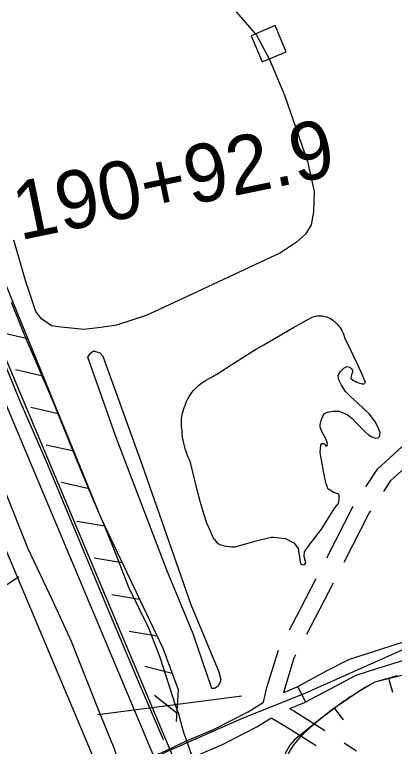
# Model space of a CAD drawing. Extents: x 3598634 to 3636690, y 517270 to 542944.
# Drawn here: x 3630353 to 3631009, y 526474 to 527737 of the extents above; entities that cross this region are included whole.
import ezdxf

# ---------------------------------------------------------------- set-up
doc = ezdxf.new("R2010")
doc.units = 0
for name, color, linetype in [('V-BLDG-OTLN', 7, 'Continuous'), ('V-BORW-LINE', 7, 'Continuous'), ('V-FLOD-BASE', 7, 'Continuous'), ('V-LEVE-TOET', 7, 'Continuous'), ('V-ROAD-CNTR', 7, 'Continuous'), ('V-RRAP-FSHR', 7, 'Continuous'), ('V-SITE-VEGE', 7, 'Continuous'), ('V-SURV-IDEN', 7, 'Continuous'), ('V-SURV-LINE', 7, 'Continuous'), ('V-TOPO-SHOR', 7, 'Continuous'), ('V-UTIL-LINE', 7, 'Continuous')]:
    doc.layers.add(name, color=color, linetype=linetype)

msp = doc.modelspace()

# ---------------------------------------------------------------- linework, layer by layer
at = {"layer": 'V-BLDG-OTLN'}
msp.add_lwpolyline([(3630802.8, 527718.4), (3630761.5, 527700.9), (3630780.7, 527655.9), (3630822, 527673.4)], close=True, dxfattribs=at)
at = {"layer": 'V-BORW-LINE'}
for p, q in [((3630998.6, 526592), (3631005.6, 526568.1)), ((3630905.2, 526539.8), (3630920.4, 526520))]:
    msp.add_line(p, q, dxfattribs=at)
for points in [[(3630975, 526585.1), (3630958, 526575.8), (3630942, 526565.5), (3630909.5, 526543.1), (3630877.9, 526518.8), (3630836.4, 526485.6), (3630828, 526476.4), (3630820.2, 526461.7), (3630819.3, 526454.1), (3630820.7, 526446.1), (3630839.1, 526398.4), (3630858.5, 526350.5), (3630899.2, 526244.1), (3630940.1, 526137.7), (3630975.5, 526048.3), (3631011.3, 525959)], [(3631013.3, 526596.3), (3630975, 526585.1)]]:
    msp.add_lwpolyline(points, dxfattribs=at)
msp.add_spline([(3630975, 526585.1), (3631052, 526605.2), (3631102.9, 526609.5), (3631126.7, 526580.9), (3631214.4, 526427.2), (3631278, 526221.5), (3631364.1, 526008.1), (3631414.5, 525862.8), (3631469.9, 525728.9), (3631500, 525646), (3631501, 525593.6), (3631358.1, 525555.8), (3631253.3, 525516), (3631197.2, 525519.2), (3631149.8, 525621.4), (3631070.3, 525800.1), (3631011.3, 525959), (3630940.1, 526137.7), (3630858.5, 526350.5), (3630820.7, 526446.1), (3630877.9, 526518.8), (3630942, 526565.5), (3630975, 526585.1)], degree=3, dxfattribs=at)
at = {"layer": 'V-FLOD-BASE'}
msp.add_lwpolyline([(3630610.3, 526485.5), (3630563.4, 526594.3), (3630517.7, 526703.7), (3630465.7, 526828.1), (3630408.7, 526964.2), (3630362.4, 527071.1), (3630323.1, 527165.5), (3630267.9, 527299.7)], dxfattribs=at)
at = {"layer": 'V-LEVE-TOET'}
for points in [[(3630347.1, 527241), (3630360.4, 527208.1), (3630373.9, 527175.3), (3630387.8, 527142.6), (3630401.9, 527110), (3630413.3, 527083.1), (3630424.6, 527056), (3630435.7, 527028.9), (3630446.7, 527001.7), (3630457.5, 526974.5)], [(3630457.5, 526974.5), (3630487.2, 526903.8), (3630508.2, 526854.3), (3630528.4, 526804.1), (3630550, 526748.8), (3630584.3, 526679), (3630603.9, 526628.3), (3630631, 526544.3), (3630636.1, 526530.6), (3630640.4, 526513.1), (3630644.8, 526498.1), (3630648, 526489), (3630654.8, 526469.5), (3630656.8, 526463.6), (3630668.3, 526444), (3630683, 526424.4), (3630709.9, 526379.4), (3630750.5, 526292.7), (3630803.2, 526169.6), (3630835.5, 526091.5), (3630882.4, 525978.8), (3630932, 525870), (3630975.1, 525771), (3631010.7, 525691.5)], [(3631057, 525246.7), (3631002.3, 525362.7), (3630957.8, 525458.5), (3630917.8, 525545.1), (3630874, 525642.2), (3630830.3, 525754.2), (3630789.7, 525844.8), (3630752.9, 525934.6), (3630722.4, 526002.4), (3630678, 526107.9), (3630642.6, 526198.4), (3630593.3, 526333.2), (3630563.5, 526402.2), (3630552.5, 526411.4), (3630546.7, 526421), (3630535.9, 526438.8), (3630525.2, 526471.4), (3630498, 526537.2), (3630451.1, 526655), (3630418.7, 526726.7), (3630376.7, 526815.3), (3630336.8, 526915)]]:
    msp.add_lwpolyline(points, dxfattribs=at)
at = {"layer": 'V-ROAD-CNTR'}
for p, q in [((3630892.1, 526799.8), (3630937.7, 526888.8)), ((3630841.3, 526577.6), (3630855.4, 526551.1)), ((3630922.1, 526480.2), (3630943.3, 526466.3))]:
    msp.add_line(p, q, dxfattribs=at)
for points in [[(3629731.6, 528159), (3630126, 527314.9), (3630608.6, 526171.2)], [(3630959.5, 526922.3), (3630979.8, 526952.7), (3631021.7, 526991.3), (3631027.7, 526993.8)], [(3630990.2, 526914.3), (3631002.7, 526933.1), (3631038.2, 526965.6), (3631065.2, 526977)], [(3630921.9, 526792.3), (3630965.3, 526876.9), (3630968, 526881)], [(3628671, 525631.8), (3630360.2, 526767.2)], [(3630827.5, 526675.6), (3630845.9, 526710.4), (3630873.8, 526764.2)], [(3630857.4, 526668.1), (3630872.5, 526696.5), (3630903.6, 526756.7)], [(3629164.8, 525508.6), (3630029.3, 526089.5), (3630473.4, 526378.3), (3630510.5, 526408.8), (3630615, 526464.9), (3630745.2, 526522.1), (3630855.8, 526566.4), (3631067.5, 526661.3)], [(3630817.8, 526567.4), (3630840.6, 526577.2), (3630892.9, 526605), (3630931.3, 526624.7), (3630967.6, 526636.4), (3631024.7, 526654.6)], [(3630828.5, 526539.4), (3630853.5, 526550.1), (3630906.8, 526578.4), (3630942.8, 526596.9), (3630976.7, 526607.9), (3631034.1, 526626.2), (3631093.1, 526646.5), (3631106, 526651.3)], [(3630782.5, 526550.4), (3630788.8, 526575.7), (3630807.8, 526638.5), (3630808.8, 526640.3)], [(3630817.6, 526567.4), (3630817.7, 526567.8), (3630835.7, 526627), (3630838.7, 526632.8)], [(3630505, 526415.5), (3630539.9, 526434.4), (3630575.1, 526451.2), (3630594.2, 526459.2), (3630606.1, 526463.2), (3630628.1, 526473.6), (3630648.7, 526483.2), (3630697.9, 526504.1), (3630756.2, 526534.1), (3630782.7, 526550.5)], [(3630828.2, 526539.3), (3630835, 526535.4), (3630888.5, 526501.9)], [(3630519.2, 526389.1), (3630553.5, 526407.6), (3630587.4, 526423.8), (3630604.8, 526431.1), (3630617.3, 526435.3), (3630640.9, 526446.5), (3630660.9, 526455.8), (3630710.6, 526476.9), (3630771, 526508), (3630795.2, 526522.9)], [(3630795.8, 526523.3), (3630819.5, 526509.7), (3630873.5, 526475.9)]]:
    msp.add_lwpolyline(points, dxfattribs=at)
at = {"layer": 'V-RRAP-FSHR'}
for p, q in [((3630375.7, 527178), (3630328, 527188.8)), ((3630402.1, 527113.2), (3630354.5, 527124)), ((3630428.6, 527048.4), (3630381, 527059.2)), ((3630455.1, 526983.6), (3630407.5, 526994.4)), ((3630481.6, 526918.8), (3630434, 526929.6)), ((3630508.9, 526854.4), (3630460.7, 526862.5)), ((3630538.9, 526791.1), (3630490.7, 526799.3)), ((3630568.9, 526727.9), (3630520.8, 526736)), ((3630598.9, 526664.6), (3630550.8, 526672.8)), ((3630625.2, 526599.8), (3630577.9, 526612.1)), ((3630633.1, 526531.7), (3630594.7, 526562))]:
    msp.add_line(p, q, dxfattribs=at)
msp.add_lwpolyline([(3630162.5, 527695.8), (3630212.7, 527580.1), (3630326.2, 527299), (3630501.9, 526869), (3630608.9, 526643.7), (3630635.4, 526572.4), (3630632.2, 526517)], dxfattribs=at)
at = {"layer": 'V-SITE-VEGE'}
msp.add_lwpolyline([(3630735.5, 527742.3), (3630770.9, 527702), (3630792.9, 527659.8), (3630818.9, 527598.2), (3630859, 527484), (3630870.4, 527432), (3630868.8, 527397.2), (3630864.9, 527374.5), (3630855.3, 527358.3), (3630839.9, 527344.6), (3630812.3, 527326.1), (3630659.5, 527255.1), (3630580.2, 527217.8), (3630529.3, 527201.5), (3630501.7, 527197.3), (3630472.9, 527194.1), (3630445.2, 527196.6), (3630433.5, 527197.6), (3630416.9, 527200), (3630399.3, 527212.4), (3630389.8, 527224.9), (3630372, 527278.4), (3630351.7, 527347.9)], dxfattribs=at)
msp.add_lwpolyline([(3630479.3, 527145.8), (3630484.3, 527153.2), (3630489.3, 527157.2), (3630500, 527153.8), (3630505.7, 527148), (3630573.2, 526959.4), (3630657.5, 526719.4), (3630705.9, 526602.7), (3630709, 526589.5), (3630708.2, 526585.4), (3630704.8, 526578), (3630698.2, 526573.9), (3630694, 526574), (3630693.2, 526575.6), (3630661.1, 526668.3), (3630616, 526778.4), (3630528.3, 527007.6)], close=True, dxfattribs=at)
at = {"layer": 'V-SURV-LINE'}
for points in [[(3630236.7, 527382.4), (3630828.3, 525975.7)], [(3630800.7, 525964.1), (3630209.1, 527370.8)]]:
    msp.add_lwpolyline(points, dxfattribs=at)
at = {"layer": 'V-TOPO-SHOR'}
for points in [[(3630655.2, 526968.8), (3630653, 526973.5), (3630651, 526978.2), (3630649.2, 526983.1), (3630647.6, 526988), (3630646.2, 526992.9), (3630645, 526997.9), (3630643.9, 527003), (3630643.1, 527008.1), (3630642.5, 527013.2), (3630642.1, 527018.4), (3630641.6, 527022.4), (3630641.2, 527026.6), (3630641.1, 527030.7), (3630641.2, 527034.8), (3630641.4, 527038.9), (3630641.9, 527043), (3630642.6, 527047.1), (3630643.5, 527051.2), (3630644.6, 527055.1), (3630645.9, 527059.1), (3630647.4, 527062.9), (3630648.9, 527066.8), (3630650.5, 527070.7), (3630652.4, 527074.4), (3630654.5, 527078.1), (3630656.7, 527081.6), (3630659.2, 527085), (3630661.8, 527088.3), (3630664.6, 527091.4), (3630667.5, 527094.4), (3630670.6, 527097.2), (3630673.9, 527099.9), (3630677.2, 527102.4), (3630680.8, 527104.7), (3630684.4, 527106.8), (3630694.1, 527112.1), (3630703.7, 527117.7), (3630713.2, 527123.5), (3630727, 527132.7), (3630740.9, 527141.7), (3630754.9, 527150.5), (3630769.1, 527159.1), (3630783.4, 527167.4), (3630799.9, 527177.3), (3630816.5, 527187), (3630833.3, 527196.5), (3630850.1, 527205.9), (3630867, 527215), (3630869.7, 527216), (3630872.4, 527216.7), (3630875.2, 527217.3), (3630878, 527217.6), (3630880.8, 527217.7), (3630883.6, 527217.5), (3630886.4, 527217.1), (3630889.2, 527216.5), (3630891.9, 527215.6), (3630894.5, 527214.6), (3630897, 527213.3), (3630899.9, 527211.6), (3630902.7, 527209.7), (3630905.4, 527207.6), (3630907.9, 527205.3), (3630910.2, 527202.9), (3630912.5, 527200.4), (3630914.5, 527197.7), (3630916.4, 527194.8), (3630918, 527191.9), (3630919.5, 527188.9), (3630920.8, 527185.7), (3630921.9, 527182.5), (3630922.8, 527179.3)], [(3630922.8, 527179.3), (3630930.1, 527164.8), (3630937.2, 527150.3), (3630944.1, 527135.6), (3630950.7, 527120.8), (3630957.1, 527106), (3630957.6, 527105.2), (3630957.9, 527104.3), (3630958.1, 527103.4), (3630958, 527102.5), (3630957.7, 527101.6), (3630957.2, 527100.9), (3630956.5, 527100.2), (3630955.7, 527099.7), (3630954.8, 527099.5), (3630953.9, 527099.4), (3630953, 527099.6), (3630952.2, 527099.9), (3630949.3, 527100.6), (3630946.4, 527101.5), (3630943.7, 527102.6), (3630941, 527103.9), (3630938.4, 527105.4), (3630936, 527107.1), (3630933.7, 527109)], [(3630880.8, 526981.5), (3630882, 526994.4), (3630883.7, 526996.8), (3630887.2, 526997), (3630888.9, 526995.3), (3630891.2, 526992.3), (3630892.7, 526993.2), (3630893.3, 526997), (3630890.3, 527005), (3630882.6, 527019.1), (3630880.5, 527025.7), (3630880.8, 527029.9), (3630882.2, 527037), (3630884.9, 527044.1), (3630887.5, 527048.4), (3630892.9, 527051), (3630903.7, 527053), (3630912.7, 527052.6), (3630927.1, 527047), (3630935.9, 527040.2), (3630942.8, 527032.6), (3630951.5, 527023.9), (3630958.2, 527017.1), (3630963.9, 527012), (3630969.5, 527008.4), (3630976, 527006.1), (3630980.5, 527006.7), (3630983.1, 527009.3), (3630984.1, 527015.6), (3630981.1, 527023.8), (3630975.2, 527035.6), (3630965.7, 527047.5), (3630945.3, 527067.1), (3630934.2, 527076.9), (3630924.4, 527086.7), (3630917.4, 527097.8), (3630912.2, 527108.2), (3630911.5, 527114.6), (3630915.8, 527121.6), (3630921.7, 527126.9), (3630926.5, 527130.2), (3630931.9, 527128.9), (3630934.2, 527126.5), (3630936.4, 527123.9), (3630936.6, 527120.2), (3630934.7, 527115.6), (3630933.3, 527111.2), (3630933.7, 527109)], [(3630655.2, 526968.8), (3630665.7, 526924), (3630672.7, 526897.5), (3630679.8, 526874.7), (3630684.2, 526860.1), (3630690.5, 526846.3), (3630696.7, 526832.6), (3630697.6, 526831.7), (3630702.1, 526826.2), (3630707.6, 526822.5), (3630714.8, 526820.6), (3630727.6, 526818.6), (3630734, 526818.6), (3630767.8, 526828.3), (3630796.1, 526835.3), (3630799.8, 526835.3), (3630820.7, 526833.2), (3630835.2, 526825.8), (3630842.4, 526815.7), (3630844.1, 526803.8), (3630846.7, 526789.2), (3630851.3, 526787.4), (3630854, 526788.3), (3630855.9, 526791), (3630853.2, 526801.9), (3630853.3, 526810.1), (3630859.8, 526819.2), (3630882.8, 526849.1), (3630906, 526886.2), (3630912.4, 526893.4), (3630913.4, 526899.8), (3630913.5, 526907.1), (3630912.6, 526909.8), (3630904.4, 526912.7), (3630894.4, 526918.2), (3630890.9, 526927.4), (3630887.4, 526942.9), (3630880.8, 526981.5)]]:
    msp.add_lwpolyline(points, dxfattribs=at)
at = {"layer": 'V-UTIL-LINE'}
msp.add_line((3630496.9, 526529.2), (3630745.2, 526561.3), dxfattribs=at)

# ---------------------------------------------------------------- texts
at = {"layer": 'V-SURV-IDEN'}
msp.add_text('190+92.9', height=100, rotation=11.6925, dxfattribs=at).set_placement((3630361.9, 527347.6))

doc.saveas('drawing.dxf')
